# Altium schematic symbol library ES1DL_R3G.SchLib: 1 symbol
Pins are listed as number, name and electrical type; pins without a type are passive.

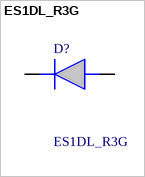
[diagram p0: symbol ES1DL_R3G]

## ES1DL_R3G
designator D?
TAIWAN SEMICONDUCTOR - ES1DL R3G - DIODE, ULTRA-FAST SMF 1A 200V; Geometry.Height: 1.43mm
footprint SODFL3618X143N
pins: 1 K, 2 A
